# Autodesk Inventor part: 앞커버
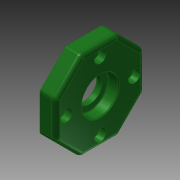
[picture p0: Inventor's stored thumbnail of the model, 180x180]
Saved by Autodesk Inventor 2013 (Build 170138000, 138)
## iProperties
Created: 2015-11
Part Number: 앞커버
Material: 알루미늄 6061
Document SubType Name: Modeling
Designer: mduedu
Density: 1 g/cm^3
Author: mduedu
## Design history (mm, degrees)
sketch "스케치5" dims "d66" = 60
  geometry: L1 (12.426, 30)-(30, 12.426); L2 (30, 12.426)-(30, -12.426); L3 (30, -12.426)-(12.426, -30); L4 (12.426, -30)-(-12.426, -30); L5 (-12.426, -30)-(-30, -12.426); L6 (-30, -12.426)-(-30, 12.426); L7 (-30, 12.426)-(-12.426, 30); L8 (-12.426, 30)-(12.426, 30); 4 further points
  constraints: 16 end point, 2 coincident, 2 vertical alignment, 1 midpoint, 19 other
extrude "돌출2" new body sketch "스케치5" distance "d67" = 11; taper "d68" = 0 deg
sketch "스케치6"
  geometry: C1 r 16 at (0, 0); 1 further point
  constraints: 1 centre point, 1 coincident
  dimensions: "d69" = 32 diameter of C1
extrude "돌출3" join sketch "스케치6" distance "d70" = 3; taper "d71" = 0 deg
hole "구멍7" diameter "d98" = 25; stored, may be unused: countersink angle "d102" = 90 deg, drill point angle "d104" = 0 deg; dims "d96" = 10, "d97" = 10, "d99" = 6, "d100" = 4, "d101" = 2, "d103" = 3
hole "구멍8" diameter "d107" = 25; stored, may be unused: countersink angle "d111" = 90 deg, drill point angle "d113" = 0 deg; dims "d108" = 6, "d109" = 4, "d110" = 2, "d112" = 7.3, "d143" = 10, "d144" = 10
hole "구멍9" diameter "d116" = 17; stored, may be unused: countersink angle "d120" = 90 deg, drill point angle "d122" = 0 deg; dims "d114" = 10, "d115" = 10, "d117" = 6, "d118" = 4, "d119" = 2, "d121" = 7.7
chamfer "모따기2" distance "d123" = 0.7; stored, may be unused: second distance "d124" = 2, angle "d125" = 30 deg
fillet "모깎기11" dims "d126" = 0.3
fillet "모깎기12" dims "d127" = 3
fillet "모깎기13" dims "d128" = 3
fillet "모깎기14" dims "d129" = 3
fillet "모깎기15" dims "d130" = 0.3
sketch "스케치8" dims "d131" = 46
  geometry: 3 further points
  constraints: 2 vertical alignment, 1 coincident, 2 other
hole "구멍10" sketch "스케치8" at (0, 23) diameter "d132" = 4.5; stored, may be unused: countersink angle "d136" = 90 deg, drill point angle "d138" = 0 deg; dims "d133" = 6, "d134" = 8, "d135" = 4.6, "d137" = 7.7
node "솔리드2"
pattern_circular "원형 패턴4" dims angle "d140" = 360 deg
